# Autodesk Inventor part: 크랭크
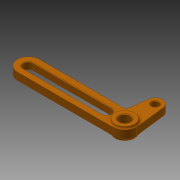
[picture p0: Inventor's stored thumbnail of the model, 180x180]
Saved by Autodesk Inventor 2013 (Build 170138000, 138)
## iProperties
Created: 2019-09
Part Number: 크랭크
Material: 알루미늄 6061
Document SubType Name: Modeling
Designer: mduedu
Density: 1 g/cm^3
Author: mduedu
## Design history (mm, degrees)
sketch "스케치1"
  geometry: L1 (0, 0)-(79, 0); L2 (0, 9)-(79, 9); L3 (10.637, -9)-(79, -9); L4 (0, 0)-(0, -25); L5 (-8.935, -1.08)-(-5.957, -25.72); L6 (7.659, -11.64)-(5.957, -25.72); L7 (79, -4)-(15, -4); L8 (15, 4)-(79, 4); C1 r 3 at (0, -25); A1 r 9 centre (0, 0) between (0, 9) and (-8.935, -1.08); A2 r 9 centre (79, 0) between (79, -9) and (79, 9); A3 r 6 centre (0, -25) between (-5.957, -25.72) and (5.957, -25.72); A4 r 3 centre (10.637, -12) between (10.637, -9) and (7.659, -11.64); A5 r 4 centre (79, 0) between (79, -4) and (79, 4); A6 r 4 centre (15, 0) between (15, -4) and (15, 4); 1 further point
  constraints: 16 end point, 13 point on circle, 12 tangent, 7 centre point, 5 coincident, 3 horizontal, 2 point on line, 1 equal radius, 1 perpendicular, 1 other
  dimensions: "d0" = 79 distance of L1.start L1.end; "d2" = 25 distance of L1.start L4.end; "d3" = 3 radius of A4; "d4" = 9 radius of A1; "d5" = 6 radius of A3; "d6" = 8 diameter of A5; "d7" = 64 distance of A6.centre L1.end; "d8" = 6 diameter of C1
extrude "돌출1" new body sketch "스케치1" stored distance "d9" = 6; taper "d10" = 0 deg
sketch "스케치2"
  geometry: C1 r 8 at (0, 0); 1 further point
  constraints: 1 centre point, 1 coincident
  dimensions: "d11" = 16 diameter of C1
extrude "돌출2" join sketch "스케치2" stored distance "d12" = 10; taper "d13" = 0 deg
sketch "스케치3"
  geometry: C1 r 4.5 at (0, 0); 1 further point
  constraints: 1 centre point, 1 coincident
  dimensions: "d14" = 9 diameter of C1
extrude "돌출3" cut sketch "스케치3" stored distance "d15" = 10; taper "d16" = 0 deg
fillet "모깎기1" dims "d17" = 2
chamfer "모따기1" distance "d18" = 0.5; stored, may be unused: second distance "d19" = 2, angle "d20" = 45 deg
node "솔리드1"
